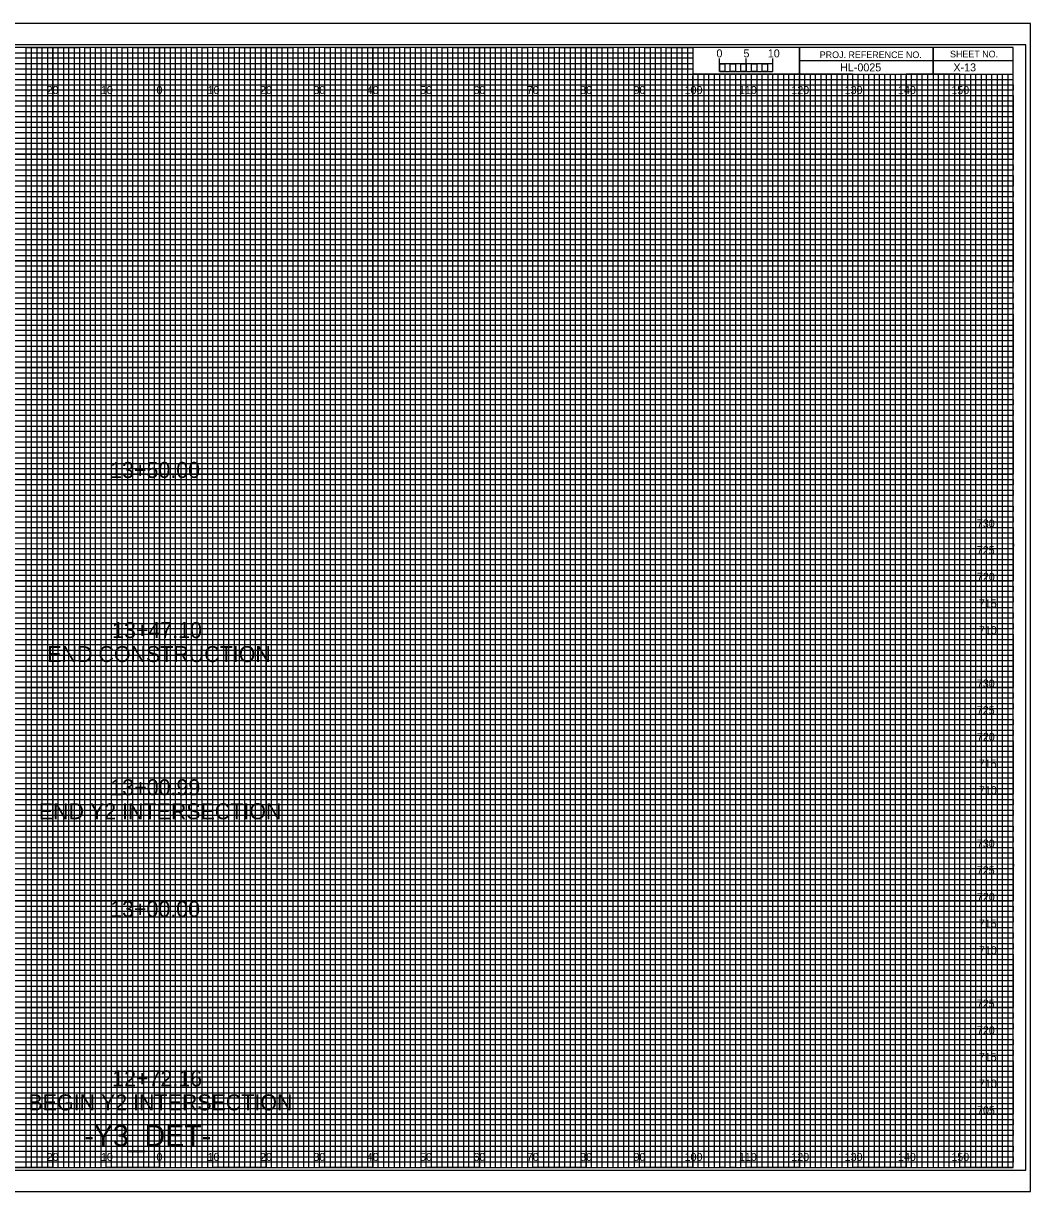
# Model space of a CAD drawing. Extents: x -13 to 323, y -5 to 434.
# Drawn here: x 134.5 to 323.3, y 215.5 to 434.5 of the extents above; entities that cross this region are included whole.
import ezdxf

# ---------------------------------------------------------------- set-up
doc = ezdxf.new("R2010")
doc.units = 0
for name, color, linetype in [('Exist CMT Pavement', 7, 'Continuous'), ('Exist Cross Section Cell', 7, 'Continuous'), ('Exist XS Center Line Elevation Label', 7, 'Continuous'), ('Exist XS Ground Line', 7, 'Continuous'), ('Prop CMT Pvmt Course 1', 7, 'Continuous'), ('Prop CMT Pvmt Course 1 Wedge', 7, 'Continuous'), ('Prop CMT Pvmt Course 2', 7, 'Continuous'), ('Prop CMT Pvmt Course 3', 7, 'Continuous'), ('Prop CMT Pvmt Surface', 7, 'Continuous'), ('Prop CMT Pvmt Surface Shoulder', 7, 'Continuous'), ('Prop CMT Shld Paved Course 1', 7, 'Continuous'), ('Prop CMT Shld Paved Course 2', 7, 'Continuous'), ('Prop CMT Shld Paved Course 3', 7, 'Continuous'), ('Prop CMT Slope Grass', 7, 'Continuous'), ('Prop CMT Subgrade Earthwork', 7, 'Continuous'), ('Prop XS Earthwork Shape', 7, 'Continuous'), ('Scratch_Level_1', 7, 'Continuous')]:
    doc.layers.add(name, color=color, linetype=linetype)

msp = doc.modelspace()

# ---------------------------------------------------------------- linework, layer by layer
at = {"layer": 'Prop CMT Pvmt Course 1'}
msp.add_lwpolyline([(-10.8, 219.5), (322.4, 219.5), (322.4, 430.5), (-10.8, 430.5)], close=True, dxfattribs=at)
at = {"layer": 'Prop CMT Pvmt Course 2'}
for p, q in [((140, 220), (140, 430)), ((150, 220), (150, 430)), ((160, 220), (160, 430)), ((170, 220), (170, 430)), ((180, 220), (180, 430)), ((190, 220), (190, 430)), ((200, 220), (200, 430)), ((210, 220), (210, 430)), ((220, 220), (220, 430)), ((230, 220), (230, 430)), ((240, 220), (240, 430)), ((250, 220), (250, 430)), ((260, 220), (260, 424.69)), ((270, 220), (270, 424.69)), ((280, 220), (280, 424.69)), ((290, 220), (290, 424.69)), ((300, 220), (300, 424.69)), ((310, 220), (310, 424.69)), ((0, 420), (320, 420)), ((0, 410), (320, 410)), ((0, 400), (320, 400)), ((0, 390), (320, 390)), ((0, 380), (320, 380)), ((0, 370), (320, 370)), ((0, 360), (320, 360)), ((0, 350), (320, 350)), ((0, 340), (320, 340)), ((0, 330), (320, 330)), ((0, 320), (320, 320)), ((0, 310), (320, 310)), ((0, 300), (320, 300)), ((0, 290), (320, 290)), ((0, 280), (320, 280)), ((0, 270), (320, 270)), ((0, 260), (320, 260)), ((0, 250), (320, 250)), ((0, 240), (320, 240)), ((0, 230), (320, 230))]:
    msp.add_line(p, q, dxfattribs=at)
at = {"layer": 'Prop CMT Pvmt Course 3'}
for p, q in [((323.3, 434.5), (-13.4, 434.5)), ((-13.4, 215.5), (323.3, 215.5))]:
    msp.add_line(p, q, dxfattribs=at)
at = {"layer": 'Prop CMT Pvmt Surface'}
for p, q in [((265, 425.49), (265, 427.9)), ((265, 426.9), (265, 427.9)), ((270, 425.49), (270, 427.9)), ((275, 425.49), (275, 427.9)), ((275, 426.9), (275, 427.9))]:
    msp.add_line(p, q, dxfattribs=at)
for points in [[(275, 426.9), (265, 426.9), (265, 425.49), (275, 425.49)], [(265, 426.9), (266, 426.9), (266, 425.49), (265, 425.49)], [(267, 426.9), (268, 426.9), (268, 425.49), (267, 425.49)], [(269, 426.9), (270, 426.9), (270, 425.49), (269, 425.49)], [(271, 426.9), (272, 426.9), (272, 425.49), (271, 425.49)], [(273, 426.9), (274, 426.9), (274, 425.49), (273, 425.49)]]:
    msp.add_lwpolyline(points, close=True, dxfattribs=at)
at = {"layer": 'Prop CMT Pvmt Surface Shoulder'}
msp.add_lwpolyline([(-13.4, 215.5), (323.3, 215.5), (323.3, 434.5), (-13.4, 434.5)], close=True, dxfattribs=at)
at = {"layer": 'Prop CMT Shld Paved Course 1'}
for points in [[(125, 220), (135, 220), (135, 430), (145, 430), (145, 220), (155, 220), (155, 430), (165, 430), (165, 220), (175, 220), (175, 430), (185, 430), (185, 220), (195, 220), (195, 430), (205, 430), (205, 220), (215, 220), (215, 430), (225, 430), (225, 220), (235, 220), (235, 430), (245, 430), (245, 220), (255, 220), (255, 430), (259.93, 430), (260, 430), (260, 425), (264.99, 425), (264.99, 220), (275, 220), (275, 425), (285, 425), (285, 220), (295, 220), (295, 425), (305, 425), (305, 220), (315, 220), (315, 425)], [(0, 425), (275, 425)], [(0, 405), (320, 405), (320, 415), (0, 415)], [(0, 385), (320, 385), (320, 395), (0, 395)], [(0, 365), (320, 365), (320, 375), (0, 375)], [(0, 345), (320, 345), (320, 355), (0, 355)], [(0, 325), (320, 325), (320, 335), (0, 335)], [(0, 305), (320, 305), (320, 315), (0, 315)], [(0, 285), (320, 285), (320, 295), (0, 295)], [(0, 265), (320, 265), (320, 275), (0, 275)], [(0, 245), (320, 245), (320, 255), (0, 255)], [(0, 225), (320, 225), (320, 235), (0, 235)]]:
    msp.add_lwpolyline(points, dxfattribs=at)
at = {"layer": 'Prop CMT Shld Paved Course 2'}
for p, q in [((0, 429), (260, 429)), ((260, 427.98), (0, 427.98)), ((260, 429), (260, 427.98)), ((0, 427), (260, 427)), ((260, 425.89), (0, 425.89)), ((260, 427), (260, 425.89)), ((0, 424), (320, 424))]:
    msp.add_line(p, q, dxfattribs=at)
for points in [[(0, 423), (270, 423), (320, 423), (320, 422), (0, 422)], [(0, 421), (320, 421), (320, 419), (0, 419)], [(0, 418), (320, 418), (320, 417), (0, 416.98)], [(0, 416), (320, 416), (320, 414), (0, 414)], [(0, 413), (320, 413), (320, 412), (0, 412)], [(0, 411), (320, 411), (320, 409), (0, 409)], [(0, 408), (320, 408), (320, 407), (0, 407)], [(0, 406), (320, 406), (320, 404), (0, 404)], [(0, 403), (320, 403), (320, 402), (0, 402)], [(0, 401), (320, 401), (320, 399), (0, 399)], [(0, 398), (320, 398), (320, 397), (0, 397)], [(0, 396), (320, 396), (320, 393.95), (320, 393), (320, 392), (0, 392)], [(0, 394), (320, 394), (320, 393), (0, 393)], [(0, 391), (320, 391), (320, 389), (0, 389.03)], [(0, 389.03), (320, 389), (320, 388), (0, 388)], [(0, 387), (320, 387), (320, 386), (0, 386)], [(0, 384), (320, 384), (320, 383), (0, 383)], [(0, 382), (320, 382), (320, 381), (0, 381)], [(-0.07, 378.89), (320, 378.89), (320, 377.88), (-0.07, 377.88)], [(0, 377), (320, 377), (320, 376), (0, 376)], [(0, 374), (320, 374), (320, 373), (0, 373)], [(0, 372), (320, 372), (320, 371), (0, 371)], [(0, 369), (320, 369), (320, 368), (0, 368)], [(0, 367), (320, 367), (320, 366), (0, 366)], [(0, 364), (320, 364), (320, 363), (0, 363)], [(0, 362), (320, 362), (320, 361), (0, 361)], [(0, 359), (320, 359), (319.99, 357.98), (0, 358)], [(0, 357), (320, 357), (320, 356), (0, 356)], [(0, 354), (320, 354), (320, 353), (0, 353)], [(0, 352), (320, 352), (320, 351), (0, 351)], [(0, 349), (320, 349), (320, 348), (0, 348)], [(0, 347), (320, 347), (320, 346), (0, 346)], [(0, 344), (320, 344), (320, 343), (0, 343)], [(0, 342), (320, 342), (320, 341), (0, 341)], [(0, 339), (320, 339), (320, 338), (0, 338)], [(0, 336.99), (320.07, 336.91), (320, 336), (0, 336)], [(0, 334), (320, 334), (320, 333), (0, 333)], [(0, 332), (320, 332), (320, 331), (0, 331)], [(0, 329), (320, 329), (320, 328), (0, 328)], [(0, 327), (320, 327), (320, 326), (0, 326)], [(0, 324), (320, 324), (320, 323), (0, 323)], [(0, 322), (320, 322), (320, 321), (0, 321)], [(0, 319), (320, 319), (320, 318), (0, 318)], [(0, 317), (320, 317), (320, 316), (0, 316)], [(0, 314), (320, 314), (320, 313), (0, 313)], [(0, 312), (320, 312), (320, 311), (0, 311)], [(0, 309), (320, 309), (320, 308), (0, 308)], [(0, 307), (320, 307), (320, 306), (0, 306)], [(0, 304), (320, 304), (320, 303), (0, 303)], [(0, 302), (320, 302), (320, 301), (0, 301)], [(0, 299), (320, 299), (319.99, 297.98), (0, 298)], [(0, 297), (320, 297), (320, 296), (0, 296)], [(0, 294), (320, 294), (320, 293), (0, 293)], [(0, 292), (320, 292), (320, 291), (0, 291)], [(0, 289), (320, 289), (320, 288), (0, 288)], [(0, 287), (320, 287), (320, 286), (0, 286)], [(0, 284), (320, 284), (320, 283), (0, 283)], [(0, 282), (320, 282), (320, 281), (0, 281)], [(0, 279), (320, 279), (320, 278), (0, 278)], [(0, 276.99), (320.07, 276.91), (320, 276), (0, 276)], [(0, 274), (320, 274), (320, 273), (0, 273)], [(0, 272), (320, 272), (320, 271), (0, 271)], [(0, 269), (320, 269), (320, 268), (0, 268)], [(0, 267), (320, 267), (320, 266), (0, 266)], [(0, 264), (320, 264), (320, 263), (0, 263)], [(0, 262), (320, 262), (320, 261), (0, 261)], [(0, 259), (320, 259), (320, 258), (0, 258)], [(0, 257), (320, 257), (320, 256), (0, 256)], [(0, 254), (320, 254), (320, 253), (0, 253)], [(0, 252), (320, 252), (320, 251), (0, 251)], [(0, 249), (320, 249), (320, 248), (0, 248)], [(0, 247), (320, 247), (320, 246), (0, 246)], [(0, 244), (320, 244), (320, 243), (0, 243)], [(0, 242), (320, 242), (320, 241), (0, 241)], [(0, 239), (320, 239), (320, 238), (0, 238)], [(0, 237), (320, 237), (320, 236), (0, 236)], [(0, 234), (320, 234), (320, 233), (0, 233)], [(0, 232), (320, 232), (320, 231), (0, 231)], [(0, 229), (320, 229), (320, 228), (0, 228)], [(0, 227), (320, 227), (320, 226), (0, 226)], [(0, 224), (320, 224), (320, 223), (0, 223)], [(0, 222), (320, 222), (320, 221), (0, 221)]]:
    msp.add_lwpolyline(points, dxfattribs=at)
at = {"layer": 'Prop CMT Shld Paved Course 3'}
for p, q in [((305, 430), (305, 425)), ((305, 425), (305, 430)), ((280, 427.5), (280, 425)), ((320, 427.49), (280, 427.49)), ((280, 425), (320, 425))]:
    msp.add_line(p, q, dxfattribs=at)
for points in [[(320, 430), (0, 430), (0, 220), (320, 220)], [(280, 430), (260, 430), (260, 425.03), (280, 425.03)], [(320, 430), (280, 430), (280, 425), (320, 425)]]:
    msp.add_lwpolyline(points, close=True, dxfattribs=at)
at = {"layer": 'Prop CMT Subgrade Earthwork'}
for p, q in [((267, 425), (266.01, 425)), ((266.01, 425), (266.01, 220)), ((267, 220), (267, 425)), ((269, 425), (268, 425)), ((268, 425), (268, 220)), ((269, 220), (269, 425)), ((266.01, 220), (265, 220)), ((268, 220), (267, 220))]:
    msp.add_line(p, q, dxfattribs=at)
for points in [[(135, 220), (136, 220), (136, 430), (137, 430), (137, 220)], [(137, 220), (138, 220), (138, 430), (139, 430), (139, 220)], [(140, 220), (141, 220), (141, 430), (142, 430), (142, 220)], [(142, 220), (143, 220), (143, 430), (144, 430), (144, 220)], [(145, 220), (146, 220), (146, 430), (147, 430), (147, 220)], [(147, 220), (148, 220), (148, 430), (149, 430), (149, 220)], [(150, 220), (151, 220), (151, 430), (152, 430), (152, 220)], [(152, 220), (153, 220), (153, 430), (154, 430), (154, 220)], [(155, 220), (156, 220), (156, 430), (157, 430), (157, 220)], [(157, 220), (158, 220), (158, 430), (159, 430), (159, 220)], [(160, 220), (161, 220), (161, 430), (162, 430), (162, 220)], [(162, 220), (163, 220), (163, 430), (164, 430), (164, 220)], [(165, 220), (166, 220), (166, 430), (167, 430), (167, 220)], [(167, 220), (168, 220), (168, 430), (169, 430), (169, 220)], [(170, 220), (171, 220), (171, 430), (172, 430), (172, 220)], [(172, 220), (173, 220), (173, 430), (174, 430), (174, 220)], [(175, 220), (176, 220), (176, 430), (177, 430), (177, 220)], [(177, 220), (178, 220), (178, 430), (179, 430), (179, 220)], [(180, 220), (181, 220), (181, 430), (182, 430), (182, 220)], [(182, 220), (183, 220), (183, 430), (184, 430), (184, 220)], [(185, 220), (186, 220), (186, 430), (187, 430), (187, 220)], [(187, 220), (188, 220), (188, 430), (189, 430), (189, 220)], [(190, 220), (191, 220), (191, 430), (192, 430), (192, 220)], [(192, 220), (193, 220), (193, 430), (194, 430), (194, 220)], [(195, 220), (196, 220), (196, 430), (197, 430), (197, 220)], [(197, 220), (198, 220), (198, 430), (199, 430), (199, 220)], [(200, 220), (201, 220), (201, 430), (202, 430), (202, 220)], [(202, 220), (203, 220), (203, 430), (204, 430), (204, 220)], [(205, 220), (206, 220), (206, 430), (207, 430), (207, 220)], [(207, 220), (208, 220), (208, 430), (209, 430), (209, 220)], [(210, 220), (211, 220), (211, 430), (212, 430), (212, 220)], [(212, 220), (213, 220), (213, 430), (214, 430), (214, 220)], [(215, 220), (216, 220), (216, 430), (217, 430), (217, 220)], [(217, 220), (218, 220), (218, 430), (219, 430), (219, 220)], [(220, 220), (221, 220), (221, 430), (222, 430), (222, 220)], [(222, 220), (223, 220), (223, 430), (224, 430), (224, 220)], [(225, 220), (226, 220), (226, 430), (227, 430), (227, 220)], [(227, 220), (228, 220), (228, 430), (229, 430), (229, 220)], [(230, 220), (231, 220), (231, 430), (232, 430), (232, 220)], [(232, 220), (233, 220), (233, 430), (234, 430), (234, 220)], [(235, 220), (236, 220), (236, 430), (237, 430), (237, 220)], [(237, 220), (238, 220), (238, 430), (239, 430), (239, 220)], [(240, 220), (241, 220), (241, 430), (242, 430), (242, 220)], [(242, 220), (243, 220), (243, 430), (244, 430), (244, 220)], [(245, 220), (246, 220), (246, 430), (247, 430), (247, 220)], [(247, 220), (248, 220), (248, 430), (249, 430), (249, 220)], [(250, 220), (251, 220), (251, 430), (252, 430), (252, 220)], [(252, 220), (253, 220), (253, 430), (254, 430), (254, 220)], [(255, 220), (256, 220), (256, 430), (257, 430), (257, 220)], [(257, 220), (258, 220), (258, 430), (259, 430), (259, 220)], [(260, 220), (261, 220), (261, 425), (262.02, 425), (262.02, 220)], [(262, 220), (263, 220), (263, 425), (263.99, 425), (263.99, 220)], [(270, 220), (270.98, 220), (270.98, 425), (272, 425), (272, 220)], [(272, 220), (273, 220), (273, 425), (274.05, 425), (274.05, 220)], [(275, 220), (276, 220), (276, 425), (277, 425), (277, 220)], [(277, 220), (278, 220), (278, 425), (279, 425), (279, 220)], [(280, 220), (281, 220), (281, 425), (282, 425), (282, 220)], [(282, 220), (283, 220), (283, 425), (284, 425), (284, 220)], [(285, 220), (286, 220), (286, 425), (287, 425), (287, 220)], [(287, 220), (288, 220), (288, 425), (289, 425), (289, 220)], [(290, 220), (291, 220), (291, 425), (292, 425), (292, 220)], [(292, 220), (293, 220), (293, 425), (294, 425), (294, 220)], [(295, 220), (296, 220), (296, 425), (297, 425), (297, 220)], [(297, 220), (298, 220), (298, 425), (299, 425), (299, 220)], [(300, 220), (301, 220), (301, 425), (302, 425), (302, 220)], [(302, 220), (303, 220), (303, 425), (304, 425), (304, 220)], [(305, 220), (306, 220), (306, 425), (307, 425), (307, 220)], [(307, 220), (308, 220), (308, 425), (309, 425), (309, 220)], [(310, 220), (311, 220), (311, 425), (312, 425), (312, 220)], [(312, 220), (313, 220), (313, 425), (314, 425), (314, 220)], [(315, 220), (316, 220), (316, 425), (317, 425), (317, 220)], [(317, 220), (318, 220), (318, 425), (319, 425), (319, 220)]]:
    msp.add_lwpolyline(points, dxfattribs=at)
at = {"layer": 'Scratch_Level_1'}
for p, q in [((150, 430), (140, 430)), ((140, 430), (140, 220)), ((150, 220), (150, 430)), ((170, 430), (160, 430)), ((160, 430), (160, 220)), ((170, 220), (170, 430)), ((190, 430), (180, 430)), ((180, 430), (180, 220)), ((190, 220), (190, 430)), ((210, 430), (200, 430)), ((200, 430), (200, 220)), ((210, 220), (210, 430)), ((230, 430), (220, 430)), ((220, 430), (220, 220)), ((230, 220), (230, 430)), ((250, 430), (240, 430)), ((240, 430), (240, 220)), ((250, 220), (250, 430)), ((260, 430), (260, 220)), ((270, 220), (270, 425)), ((290, 425), (280, 425)), ((280, 425), (280, 220)), ((290, 220), (290, 425)), ((310, 425), (300, 425)), ((300, 425), (300, 220)), ((310, 220), (310, 425)), ((140, 220), (130, 220)), ((160, 220), (150, 220)), ((180, 220), (170, 220)), ((200, 220), (190, 220)), ((220, 220), (210, 220)), ((240, 220), (230, 220)), ((260, 220), (250, 220)), ((280, 220), (270, 220)), ((300, 220), (290, 220)), ((320, 220), (310, 220)), ((320, 220), (320, 220))]:
    msp.add_line(p, q, dxfattribs=at)
for points in [[(0, 420), (320, 420), (320, 410), (0, 410)], [(0, 400), (320, 400), (320, 390), (0, 390)], [(0, 380), (320, 380), (320, 370), (0, 370)], [(0, 360), (320, 360), (320, 350), (0, 350)], [(0, 340), (320, 340), (320, 330), (0, 330)], [(0, 320), (320, 320), (320, 310), (0, 310)], [(0, 300), (320, 300), (320, 290), (0, 290)], [(0, 280), (320, 280), (320, 270), (0, 270)], [(0, 260), (320, 260), (320, 250), (0, 250)], [(0, 240), (320, 240), (320, 230), (0, 230)]]:
    msp.add_lwpolyline(points, dxfattribs=at)

# ---------------------------------------------------------------- texts
at = {"layer": 'Exist CMT Pavement'}
for s, p in [('5', (269.47, 428.12)), ('10', (274.04, 428.12))]:
    msp.add_text(s, height=1.5, dxfattribs=at).set_placement(p)
at = {"layer": 'Exist Cross Section Cell'}
for s, p in [('20', (138.86, 421.25)), ('10', (149.04, 421.25)), ('0', (159.45, 421.25)), ('0', (159.45, 421.25)), ('10', (169.04, 421.25)), ('20', (178.86, 421.25)), ('30', (188.86, 421.25)), ('40', (198.86, 421.25)), ('50', (208.86, 421.25)), ('60', (218.86, 421.25)), ('70', (228.86, 421.25)), ('80', (238.86, 421.25)), ('90', (248.86, 421.25)), ('100', (258.44, 421.25)), ('110', (268.62, 421.25)), ('120', (278.44, 421.25)), ('130', (288.44, 421.25)), ('140', (298.44, 421.25)), ('150', (308.44, 421.25)), ('20', (138.86, 221.25)), ('10', (149.04, 221.25)), ('0', (159.45, 221.25)), ('0', (159.45, 221.25)), ('10', (169.04, 221.25)), ('20', (178.86, 221.25)), ('30', (188.86, 221.25)), ('40', (198.86, 221.25)), ('50', (208.86, 221.25)), ('60', (218.86, 221.25)), ('70', (228.86, 221.25)), ('80', (238.86, 221.25)), ('90', (248.86, 221.25)), ('100', (258.44, 221.25)), ('110', (268.62, 221.25)), ('120', (278.44, 221.25)), ('130', (288.44, 221.25)), ('140', (298.44, 221.25)), ('150', (308.44, 221.25))]:
    msp.add_text(s, height=1.5, dxfattribs=at).set_placement(p)
at = {"layer": 'Exist XS Center Line Elevation Label'}
msp.add_text('X-13', height=1.5, dxfattribs=at).set_placement((308.83, 425.5))
at = {"layer": 'Exist XS Ground Line'}
for s, p in [('13+50.00', (150.77, 349.28)), ('13+47.10', (151.13, 319.27)), ('END CONSTRUCTION', (138.99, 314.77)), ('13+00.99', (150.81, 289.8)), ('END Y2 INTERSECTION', (137.39, 285.3)), ('13+00.00', (150.77, 266.98)), ('12+72.16', (151.15, 235.23)), ('BEGIN Y2 INTERSECTION', (135.45, 230.73))]:
    msp.add_text(s, height=3, dxfattribs=at).set_placement(p)
at = {"layer": 'Prop CMT Pvmt Course 1 Wedge'}
msp.add_text('-Y3_DET-', height=4, dxfattribs=at).set_placement((145.93, 224))
at = {"layer": 'Prop CMT Pvmt Surface'}
msp.add_text('0', height=1.5, dxfattribs=at).set_placement((264.41, 428.12))
at = {"layer": 'Prop CMT Shld Paved Course 3'}
for s, p in [('PROJ. REFERENCE NO.', (283.77, 427.99)), ('SHEET NO.', (308.19, 428.12))]:
    msp.add_text(s, height=1.25, dxfattribs=at).set_placement(p)
at = {"layer": 'Prop CMT Slope Grass'}
for s, p in [('730', (313.22, 340)), ('725', (313.21, 335)), ('720', (313.23, 330)), ('715', (313.59, 325)), ('710', (313.61, 320)), ('730', (313.22, 310)), ('725', (313.21, 305)), ('720', (313.23, 300)), ('715', (313.59, 295)), ('710', (313.61, 290)), ('730', (313.22, 280)), ('725', (313.21, 275)), ('720', (313.23, 270)), ('715', (313.59, 265)), ('710', (313.61, 260)), ('725', (313.21, 250)), ('720', (313.23, 245)), ('715', (313.59, 240)), ('710', (313.61, 235)), ('705', (313.26, 230))]:
    msp.add_text(s, height=1.5, dxfattribs=at).set_placement(p)
at = {"layer": 'Prop XS Earthwork Shape'}
msp.add_text('HL-0025', height=1.5, dxfattribs=at).set_placement((287.6, 425.5))

doc.saveas('drawing.dxf')
